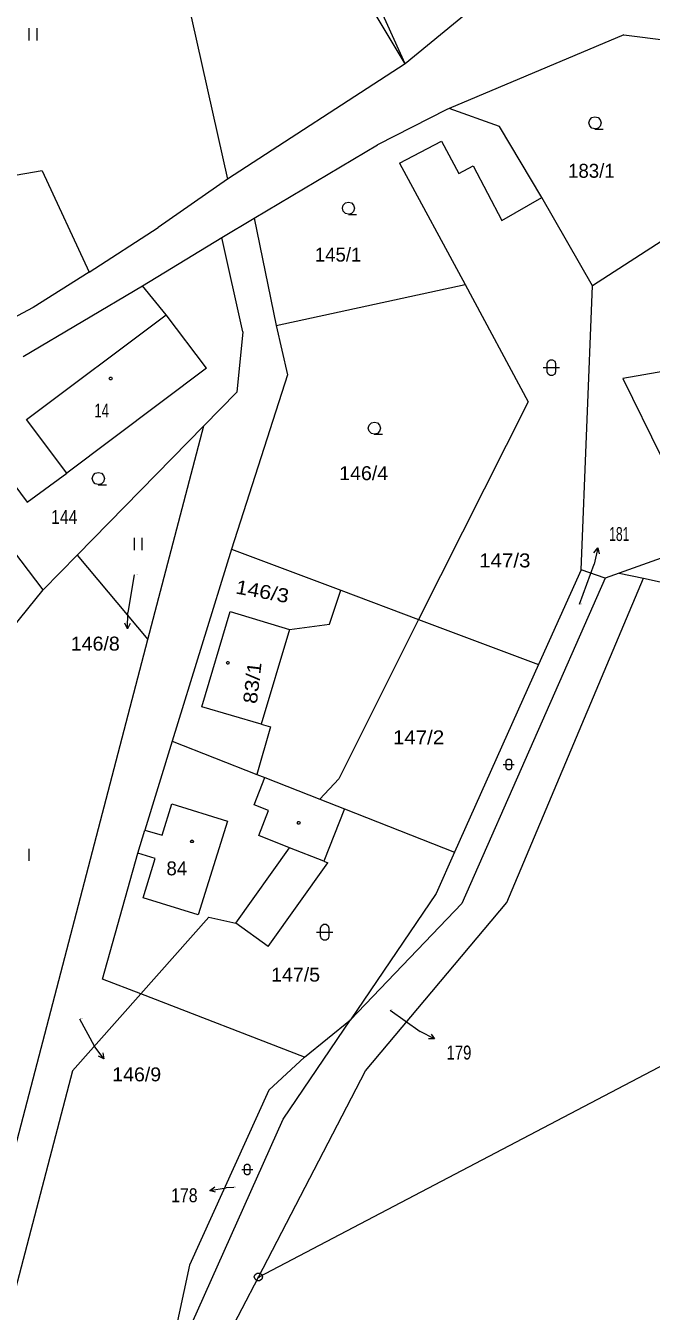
# Model space of a CAD drawing. Extents: x -687390 to -684106, y -954833 to -951648.
# Drawn here: x -686858.8 to -686782.5, y -952530.5 to -952373.7 of the extents above; entities that cross this region are included whole.
import ezdxf
from ezdxf.enums import TextEntityAlignment as Align

# ---------------------------------------------------------------- set-up
doc = ezdxf.new("R2010")
doc.units = 0
doc.header["$LTSCALE"] = 0.68
for name, color, linetype, lineweight in [('1', 7, 'Continuous', 13), ('3', 7, 'Continuous', 13), ('4', 7, 'Continuous', 13), ('5', 7, 'Continuous', 13), ('7', 7, 'Continuous', 13), ('8', 7, 'Continuous', 13)]:
    doc.layers.add(name, color=color, linetype=linetype, lineweight=lineweight)
doc.layers.add('2', color=7, linetype='Continuous')

msp = doc.modelspace()

# ---------------------------------------------------------------- linework, layer by layer
at = {"layer": '1'}
for p, q in [((-686843.35, -952351.48), (-686834.2, -952392.4)), ((-686812.53, -952378.29), (-686825.09, -952350.41)), ((-686785.8, -952374.77), (-686807.16, -952383.76)), ((-686785.8, -952374.77), (-686780.33, -952375.48)), ((-686812.53, -952378.29), (-686834.2, -952392.4)), ((-686807.44, -952383.88), (-686815.88, -952388.18)), ((-686830.94, -952397.16), (-686815.88, -952388.18)), ((-686856.83, -952391.38), (-686889.27, -952396.93)), ((-686856.83, -952391.38), (-686851.11, -952403.75)), ((-686834.2, -952392.4), (-686842.67, -952398.29)), ((-686851.11, -952403.75), (-686842.67, -952398.29)), ((-686844.57, -952405.39), (-686834.88, -952399.51)), ((-686851.11, -952403.75), (-686857.91, -952408.06)), ((-686859.13, -952414.04), (-686844.57, -952405.39)), ((-686841.69, -952408.93), (-686844.57, -952405.39)), ((-686857.91, -952408.06), (-686863.23, -952410.86)), ((-686836.78, -952415.46), (-686841.69, -952408.93)), ((-686828.27, -952410.25), (-686826.89, -952416.28)), ((-686836.78, -952415.46), (-686853.8, -952428.27)), ((-686826.89, -952416.28), (-686833.72, -952437.52)), ((-686837.09, -952422.47), (-686852.56, -952438.27)), ((-686858.66, -952431.82), (-686853.8, -952428.27)), ((-686833.72, -952437.52), (-686840.94, -952460.96)), ((-686833.72, -952437.52), (-686820.35, -952442.55)), ((-686852.56, -952438.27), (-686856.69, -952442.48)), ((-686791.04, -952440.04), (-686796.22, -952451.63)), ((-686786.38, -952440.47), (-686788.11, -952441.09)), ((-686786.38, -952440.47), (-686783.43, -952441.09)), ((-686788.11, -952441.09), (-686805.6, -952480.76)), ((-686783.43, -952441.09), (-686765.07, -952445)), ((-686820.35, -952442.55), (-686810.89, -952446.11)), ((-686833.88, -952445.16), (-686826.63, -952447.32)), ((-686810.89, -952446.11), (-686820.6, -952465.57)), ((-686865.02, -952529.26), (-686843.91, -952448.54)), ((-686796.22, -952451.63), (-686806.47, -952474.53)), ((-686840.94, -952460.96), (-686844.29, -952471.83)), ((-686840.94, -952460.96), (-686830.63, -952465.03)), ((-686830.63, -952465.03), (-686829.64, -952465.42)), ((-686829.64, -952465.42), (-686822.94, -952468.05)), ((-686820.6, -952465.57), (-686822.94, -952468.05)), ((-686822.94, -952468.05), (-686819.91, -952469.24)), ((-686819.91, -952469.24), (-686822.43, -952475.63)), ((-686819.91, -952469.24), (-686806.47, -952474.53)), ((-686845.14, -952474.65), (-686844.29, -952471.83)), ((-686849.47, -952490.01), (-686845.14, -952474.65)), ((-686806.47, -952474.53), (-686808.72, -952479.56)), ((-686829.24, -952486.01), (-686821.95, -952475.82)), ((-686822.43, -952475.63), (-686821.95, -952475.82)), ((-686808.72, -952479.56), (-686819.18, -952494.97)), ((-686805.6, -952480.76), (-686819.18, -952494.97)), ((-686836.48, -952482.44), (-686844.8, -952491.82)), ((-686836.48, -952482.44), (-686833.19, -952483.16)), ((-686829.24, -952486.01), (-686833.19, -952483.16)), ((-686844.8, -952491.82), (-686849.47, -952490.01)), ((-686827.4, -952507.1), (-686819.18, -952494.97)), ((-686824.8, -952499.55), (-686819.18, -952494.97)), ((-686829.17, -952503.57), (-686824.8, -952499.55)), ((-686853.14, -952501.21), (-686871.22, -952570.41)), ((-686830.43, -952526.36), (-686817.36, -952501.18)), ((-686838.55, -952532.05), (-686827.4, -952507.1)), ((-686838.48, -952541.86), (-686830.43, -952526.36))]:
    msp.add_line(p, q, dxfattribs=at)
for points in [[(-686812.53, -952378.29), (-686823.77, -952359.47), (-686841.22, -952338.37)], [(-686749.13, -952369.49), (-686783.59, -952365.56), (-686792.79, -952366.48), (-686803.43, -952370.86), (-686812.53, -952378.29)], [(-686777.91, -952397.85), (-686789.63, -952405.39), (-686795.83, -952394.62), (-686800.98, -952385.97), (-686807.16, -952383.76), (-686807.44, -952383.88)], [(-686813.22, -952390.44), (-686808.06, -952387.73), (-686805.96, -952391.69), (-686804.23, -952390.76), (-686800.73, -952397.41), (-686795.83, -952394.62)], [(-686813.22, -952390.44), (-686805.19, -952405.22), (-686797.48, -952419.54)], [(-686832.33, -952411.03), (-686834.88, -952399.51), (-686830.94, -952397.16)], [(-686830.94, -952397.16), (-686828.27, -952410.25), (-686805.19, -952405.22)], [(-686788.11, -952441.09), (-686791.04, -952440.04), (-686789.63, -952405.39)], [(-686832.33, -952411.03), (-686833.08, -952418.36), (-686837.09, -952422.47)], [(-686774.98, -952414.79), (-686785.93, -952416.7), (-686781.27, -952426.24), (-686768.61, -952434.13), (-686786.38, -952440.47)], [(-686797.48, -952419.54), (-686810.89, -952446.11), (-686796.22, -952451.63)], [(-686870.41, -952424.48), (-686866.7, -952420.99), (-686858.66, -952431.82)], [(-686852.56, -952438.27), (-686843.91, -952448.54), (-686837.09, -952422.47)], [(-686867.96, -952456.42), (-686856.69, -952442.48), (-686870.41, -952424.48)], [(-686817.36, -952501.18), (-686800.11, -952480.66), (-686783.43, -952441.09)], [(-686826.63, -952447.32), (-686821.76, -952446.7), (-686820.35, -952442.55)], [(-686830.09, -952458.91), (-686837.33, -952456.76), (-686833.88, -952445.16)], [(-686830.09, -952458.91), (-686828.96, -952459.23), (-686830.63, -952465.03)], [(-686830.43, -952526.36), (-686777.42, -952498.58), (-686718.6, -952467.74)], [(-686824.8, -952499.55), (-686844.8, -952491.82), (-686853.14, -952501.21)], [(-686829.17, -952503.57), (-686838.84, -952524.91), (-686842.04, -952539.83), (-686838.55, -952532.05)]]:
    msp.add_lwpolyline(points, dxfattribs=at)
at = {"layer": '3'}
for p, q in [((-686858.44, -952373.96), (-686858.44, -952375.46)), ((-686857.44, -952375.46), (-686857.44, -952373.96)), ((-686845.6, -952436.17), (-686845.6, -952437.67)), ((-686844.6, -952437.67), (-686844.6, -952436.17)), ((-686858.43, -952475.59), (-686858.43, -952474.09))]:
    msp.add_line(p, q, dxfattribs=at)
for points in [[(-686789.33, -952386.25), (-686789.71, -952386.15), (-686789.98, -952385.88), (-686790.08, -952385.51), (-686789.98, -952385.14), (-686789.71, -952384.87), (-686789.34, -952384.77), (-686788.97, -952384.87), (-686788.7, -952385.14), (-686788.6, -952385.52), (-686788.7, -952385.9), (-686788.97, -952386.17), (-686789.35, -952386.27), (-686788.35, -952386.27)], [(-686819.43, -952396.67), (-686819.81, -952396.57), (-686820.08, -952396.3), (-686820.18, -952395.93), (-686820.08, -952395.56), (-686819.81, -952395.29), (-686819.44, -952395.19), (-686819.07, -952395.29), (-686818.8, -952395.56), (-686818.7, -952395.94), (-686818.8, -952396.32), (-686819.07, -952396.59), (-686819.45, -952396.69), (-686818.45, -952396.69)], [(-686795.67, -952415.38), (-686794.4, -952415.38), (-686793.67, -952415.38)], [(-686816.26, -952423.5), (-686816.64, -952423.4), (-686816.91, -952423.13), (-686817.01, -952422.76), (-686816.91, -952422.39), (-686816.64, -952422.12), (-686816.27, -952422.02), (-686815.9, -952422.12), (-686815.63, -952422.39), (-686815.53, -952422.77), (-686815.63, -952423.15), (-686815.9, -952423.42), (-686816.28, -952423.52), (-686815.28, -952423.52)], [(-686849.96, -952429.65), (-686850.34, -952429.55), (-686850.61, -952429.28), (-686850.71, -952428.91), (-686850.61, -952428.54), (-686850.34, -952428.27), (-686849.97, -952428.17), (-686849.6, -952428.27), (-686849.33, -952428.54), (-686849.23, -952428.92), (-686849.33, -952429.3), (-686849.6, -952429.57), (-686849.98, -952429.67), (-686848.98, -952429.67)], [(-686800.53, -952463.8), (-686799.679, -952463.8), (-686799.19, -952463.8)], [(-686823.33, -952484.28), (-686822.06, -952484.28), (-686821.33, -952484.28)], [(-686832.47, -952513.25), (-686831.619, -952513.25), (-686831.13, -952513.25)]]:
    msp.add_lwpolyline(points, dxfattribs=at)
for points in [[(-686795.17, -952414.88), (-686795.07, -952414.59), (-686794.82, -952414.41), (-686794.51, -952414.41), (-686794.26, -952414.59), (-686794.16, -952414.88), (-686794.16, -952415.88), (-686794.26, -952416.17), (-686794.51, -952416.35), (-686794.82, -952416.35), (-686795.07, -952416.17), (-686795.17, -952415.88)], [(-686800.195, -952463.465), (-686800.128, -952463.271), (-686799.96, -952463.15), (-686799.753, -952463.15), (-686799.585, -952463.271), (-686799.518, -952463.465), (-686799.518, -952464.135), (-686799.585, -952464.329), (-686799.753, -952464.45), (-686799.96, -952464.45), (-686800.128, -952464.329), (-686800.195, -952464.135)], [(-686822.83, -952483.78), (-686822.73, -952483.49), (-686822.48, -952483.31), (-686822.17, -952483.31), (-686821.92, -952483.49), (-686821.82, -952483.78), (-686821.82, -952484.78), (-686821.92, -952485.07), (-686822.17, -952485.25), (-686822.48, -952485.25), (-686822.73, -952485.07), (-686822.83, -952484.78)], [(-686832.135, -952512.915), (-686832.068, -952512.721), (-686831.9, -952512.6), (-686831.693, -952512.6), (-686831.525, -952512.721), (-686831.458, -952512.915), (-686831.458, -952513.585), (-686831.525, -952513.779), (-686831.693, -952513.9), (-686831.9, -952513.9), (-686832.068, -952513.779), (-686832.135, -952513.585)]]:
    msp.add_lwpolyline(points, close=True, dxfattribs=at)
at = {"layer": '4'}
for p, q in [((-686826.63, -952447.32), (-686830.09, -952458.91)), ((-686830.93, -952468.74), (-686829.64, -952465.42)), ((-686826.62, -952473.97), (-686830.38, -952472.48)), ((-686833.19, -952483.16), (-686826.62, -952473.97)), ((-686822.43, -952475.63), (-686826.62, -952473.97))]:
    msp.add_line(p, q, dxfattribs=at)
for points in [[(-686853.8, -952428.27), (-686858.73, -952421.7), (-686841.69, -952408.93)], [(-686844.29, -952471.83), (-686842.18, -952472.45), (-686841, -952468.61), (-686834.22, -952470.71), (-686837.77, -952482.15), (-686844.5, -952480.1)], [(-686830.38, -952472.48), (-686829.2, -952469.42), (-686830.93, -952468.74)], [(-686844.5, -952480.1), (-686843.05, -952475.29), (-686845.14, -952474.65)]]:
    msp.add_lwpolyline(points, dxfattribs=at)
at = {"layer": '5'}
for points in [[(-686848.37, -952416.56), (-686848.28, -952416.71), (-686848.37, -952416.86), (-686848.55, -952416.86), (-686848.64, -952416.71), (-686848.55, -952416.56)], [(-686834.07, -952451.25), (-686833.98, -952451.4), (-686834.07, -952451.55), (-686834.25, -952451.55), (-686834.34, -952451.4), (-686834.25, -952451.25)], [(-686825.41, -952470.79), (-686825.32, -952470.94), (-686825.41, -952471.09), (-686825.59, -952471.09), (-686825.68, -952470.94), (-686825.59, -952470.79)], [(-686838.45, -952473.05), (-686838.36, -952473.2), (-686838.45, -952473.35), (-686838.63, -952473.35), (-686838.72, -952473.2), (-686838.63, -952473.05)]]:
    msp.add_lwpolyline(points, close=True, dxfattribs=at)
at = {"layer": '7'}
for p, q in [((-686789.009, -952437.385), (-686789.43, -952439.35)), ((-686791.23, -952444.26), (-686789.43, -952439.35)), ((-686845.59, -952440.68), (-686846.37, -952445.25)), ((-686846.425, -952447.259), (-686846.37, -952445.25)), ((-686814.36, -952493.79), (-686810.7, -952496.39)), ((-686852.28, -952494.85), (-686850.5, -952498.14)), ((-686808.912, -952497.308), (-686810.7, -952496.39)), ((-686849.301, -952499.753), (-686850.5, -952498.14)), ((-686836.363, -952515.797), (-686834.38, -952515.47)), ((-686833.44, -952515.45), (-686834.38, -952515.47))]:
    msp.add_line(p, q, dxfattribs=at)
for points in [[(-686789.477, -952437.97), (-686789.009, -952437.385), (-686788.822, -952438.11)], [(-686846.072, -952446.599), (-686846.425, -952447.259), (-686846.742, -952446.58)], [(-686809.355, -952496.704), (-686808.912, -952497.308), (-686809.661, -952497.3)], [(-686849.432, -952499.015), (-686849.301, -952499.753), (-686849.969, -952499.415)], [(-686835.648, -952516.018), (-686836.363, -952515.797), (-686835.757, -952515.357)]]:
    msp.add_lwpolyline(points, dxfattribs=at)
at = {"layer": '8'}
msp.add_line((-686830.55, -952526.36), (-686830.31, -952526.36), dxfattribs=at)
msp.add_lwpolyline([(-686830.28, -952525.88), (-686830.03, -952526.06), (-686829.93, -952526.35), (-686830.03, -952526.64), (-686830.28, -952526.82), (-686830.59, -952526.82), (-686830.84, -952526.64), (-686830.94, -952526.35), (-686830.84, -952526.06), (-686830.59, -952525.88)], close=True, dxfattribs=at)

# ---------------------------------------------------------------- texts
at = {"layer": '2'}
for s, p in [('183/1', (-686792.625, -952392.21)), ('145/1', (-686823.545, -952402.44)), ('84', (-686841.655, -952477.34))]:
    msp.add_text(s, height=1.7, dxfattribs=at).set_placement(p)
for s, height, width, p in [('14', 1.7, 0.7, (-686850.445, -952421.46)), ('146/4', 1.7, 1.05, (-686820.565, -952429.11)), ('144', 1.7, 0.85, (-686855.745, -952434.46)), ('147/3', 1.7, 1.1, (-686803.475, -952439.76)), ('146/8', 0.1, 1.05, (-686845.544, -952440.68)), ('181', 0.1, 0.65, (-686791.184, -952444.26)), ('147/2', 1.7, 1.1, (-686814.005, -952461.35)), ('147/5', 1.7, 1.05, (-686828.875, -952490.31)), ('179', 0.1, 0.8, (-686814.314, -952493.79)), ('146/9', 0.1, 1.05, (-686852.234, -952494.85)), ('178', 0.1, 0.85, (-686833.394, -952515.45))]:
    msp.add_text(s, height=height, dxfattribs=dict(at, width=width)).set_placement(p)
at = {"layer": '2', "width": 1.15}
for s, rotation, p in [('146/3', 349.562, (-686833.308, -952442.932)), ('83/1', 83.308, (-686830.625, -952456.468))]:
    msp.add_text(s, height=1.7, rotation=rotation, dxfattribs=at).set_placement(p)
at = {"layer": '7'}
for s, width, p in [('181', 0.65, (-686787.605, -952436.54)), ('179', 0.8, (-686807.465, -952499.82)), ('146/9', 1.05, (-686848.275, -952502.48))]:
    msp.add_text(s, height=1.7, dxfattribs=dict(at, width=width)).set_placement(p)
for s, width, p in [('146/8', 1.05, (-686847.356, -952449.91)), ('178', 0.85, (-686837.856, -952517.23))]:
    msp.add_text(s, height=1.7, dxfattribs=dict(at, width=width)).set_placement(p, align=Align.RIGHT)

doc.saveas('drawing.dxf')
